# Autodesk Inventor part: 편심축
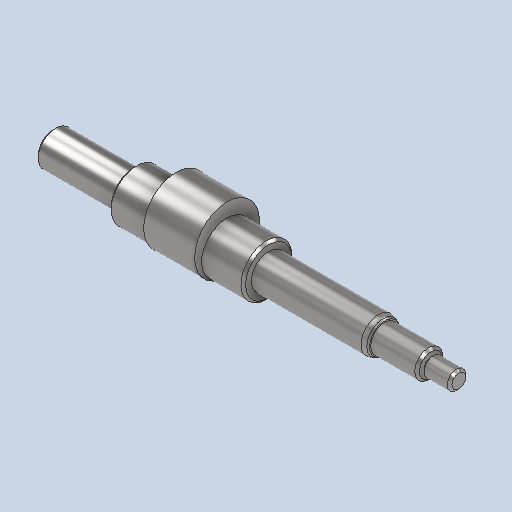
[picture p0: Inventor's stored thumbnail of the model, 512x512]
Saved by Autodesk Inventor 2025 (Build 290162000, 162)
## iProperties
Created: 2024-07
Part Number: 편심축
Material: 강철, 연강
Document SubType Name: Modeling
Designer: parkm
Density: 7.86 g/cm^3
Appearance: 기본값
Author: jhkim
Sending System: Autodesk Inventor 2025
Preprocessor: ST-DEVELOPER v20
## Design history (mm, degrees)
feature "솔리드1"
node "솔리드2"
